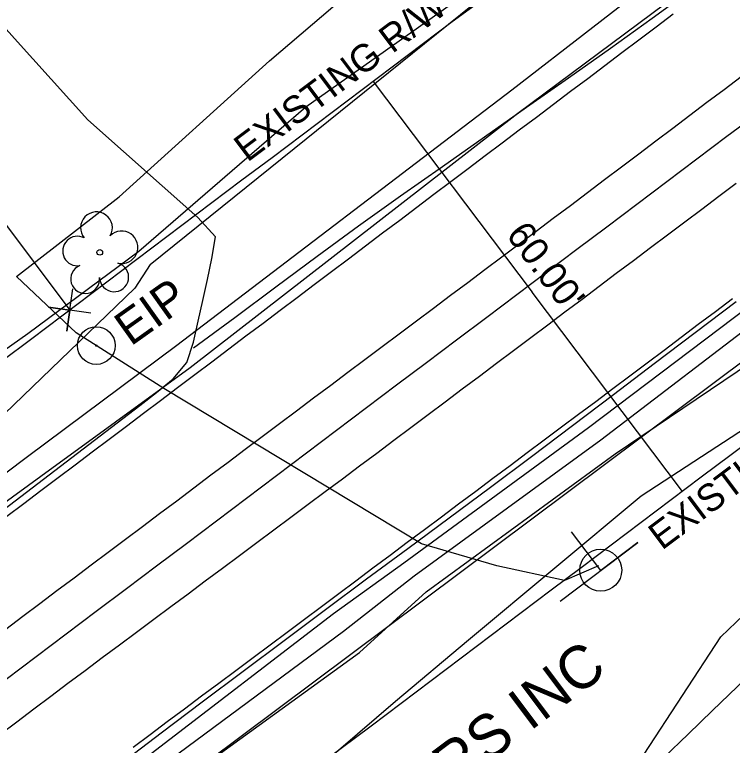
# Model space of a CAD drawing. Extents: x 2186615 to 2188822, y 629899 to 631820.
# Drawn here: x 2186940.8 to 2187024.7, y 630222.6 to 630308 of the extents above; entities that cross this region are included whole.
import ezdxf

# ---------------------------------------------------------------- set-up
doc = ezdxf.new("R2010")
doc.units = 0
for name, color, linetype in [('Exist Horizontal Alignment', 7, 'Continuous'), ('Exist Property Corner CELL', 7, 'Continuous'), ('Exist Property Iron Pin CELL', 7, 'Continuous'), ('Exist Property Iron Pin Text', 7, 'Continuous'), ('Exist Property Line', 7, 'Continuous'), ('Exist Property Owner Text', 7, 'Continuous'), ('Exist Right of Way Line', 7, 'Continuous'), ('Exist Right of Way Line Text', 7, 'Continuous'), ('Exist Right of Way Width CELL', 7, 'Continuous'), ('Exist Roads EOP', 7, 'Continuous'), ('Exist Roads EOP Other', 7, 'Continuous'), ('Exist Roads EOT', 7, 'Continuous'), ('Exist Utilities Gas UG Line SUE LOS B', 7, 'Continuous'), ('Exist Utilities Power Joint Use Telephone CELL', 7, 'Continuous'), ('Exist Utilities Sanitary Sewer UG Line', 7, 'Continuous'), ('Exist Utilities Telephone UG Cable SUE LOS C', 7, 'Continuous'), ('Exist Utilities Telephone UG FO SUE LOS B', 7, 'Continuous'), ('Exist Utilities TV UG Cable SUE LOS B', 7, 'Continuous'), ('Exist Utilities TV UG FO Cable SUE LOS B', 7, 'Continuous'), ('Exist Utilities Water UG Line SUE LOS B', 7, 'Continuous'), ('Exist Vegetation Tree CELL', 7, 'Continuous'), ('Exist Vegetation Woods Line', 7, 'Continuous'), ('Scratch_Level_1', 7, 'Continuous')]:
    doc.layers.add(name, color=color, linetype=linetype)

msp = doc.modelspace()

# ---------------------------------------------------------------- linework, layer by layer
at = {"layer": 'Exist Horizontal Alignment'}
msp.add_arc((2232330.704, 570095.737), 75342.476, 126.85926308, 127.07301977, dxfattribs=at)
at = {"layer": 'Exist Property Corner CELL'}
msp.add_line((2186947.272, 630273.425), (2186947.272, 630273.425), dxfattribs=at)
msp.add_lwpolyline([(2186949.746, 630273.07), (2186944.797, 630273.781), (2186947.272, 630273.425), (2186946.916, 630270.951), (2186947.627, 630275.9)], dxfattribs=at)
at = {"layer": 'Exist Property Iron Pin CELL'}
for radius in [2.203, 0.0707]:
    msp.add_circle((2186950.378, 630269.278), radius, dxfattribs=at)
at = {"layer": 'Exist Property Line'}
msp.add_line((2186817.153, 630447.151), (2186947.272, 630273.425), dxfattribs=at)
at = {"layer": 'Exist Right of Way Line'}
for centre, radius, start, end in [((2189028.8, 628141.736), 2893.554, 125.65722, 135.708207), ((2232330.704, 570095.737), 75372.476, 126.85926308, 127.07301977), ((2232330.704, 570095.737), 75312.476, 126.85926308, 127.07301977)]:
    msp.add_arc(centre, radius, start, end, dxfattribs=at)
at = {"layer": 'Exist Right of Way Width CELL'}
for p in [(2186982.724, 630300.145), (2187018.823, 630252.22)]:
    msp.add_line(p, (2187001.279, 630275.511), dxfattribs=at)
at = {"layer": 'Exist Roads EOP'}
for points in [[(2186961.722, 630269.005), (2186966.542, 630272.577), (2186971.362, 630276.149), (2186976.183, 630279.718), (2186981.013, 630283.275), (2186985.89, 630286.768), (2186990.796, 630290.22), (2186995.703, 630293.671), (2187000.61, 630297.122), (2187005.515, 630300.577), (2187010.416, 630304.037), (2187015.298, 630307.524), (2187020.127, 630311.083)], [(2186939.56, 630250.133), (2186941.546, 630251.649), (2186943.532, 630253.165), (2186945.518, 630254.682), (2186947.503, 630256.198), (2186949.489, 630257.715), (2186951.474, 630259.233), (2186953.459, 630260.752), (2186955.441, 630262.273), (2186957.419, 630263.801), (2186959.352, 630265.385), (2186960.941, 630267.309), (2186961.723, 630269.679), (2186962.287, 630272.115), (2186962.835, 630274.554), (2186963.362, 630276.997), (2186963.853, 630279.448), (2186964.3, 630282.004)], [(2187025.121, 630274.377), (2187020.333, 630270.762), (2187015.546, 630267.147), (2187010.763, 630263.527), (2187005.981, 630259.905), (2187001.199, 630256.283), (2186996.408, 630252.675), (2186991.587, 630249.107), (2186986.764, 630245.541), (2186981.944, 630241.973), (2186977.139, 630238.384), (2186972.335, 630234.793), (2186967.532, 630231.203), (2186962.743, 630227.593), (2186957.963, 630223.972), (2186953.183, 630220.351)]]:
    msp.add_lwpolyline(points, dxfattribs=at)
at = {"layer": 'Exist Roads EOP Other'}
for p, q in [((2186962.235, 630284.243), (2186949.393, 630295.672)), ((2186964.3, 630282.004), (2186962.235, 630284.243))]:
    msp.add_line(p, q, dxfattribs=at)
msp.add_lwpolyline([(2186925.022, 630323.205), (2186930.536, 630316.971), (2186934.644, 630312.092), (2186940.815, 630305.172), (2186949.393, 630295.672)], dxfattribs=at)
at = {"layer": 'Exist Roads EOT'}
for points in [[(2186939.924, 630249.331), (2186941.919, 630250.835), (2186943.914, 630252.34), (2186945.909, 630253.845), (2186947.904, 630255.349), (2186949.899, 630256.854), (2186951.894, 630258.359), (2186953.889, 630259.863), (2186955.885, 630261.368), (2186957.88, 630262.873), (2186959.875, 630264.378), (2186961.871, 630265.883), (2186963.866, 630267.388), (2186965.861, 630268.893), (2186967.856, 630270.399), (2186969.851, 630271.904), (2186971.847, 630273.409), (2186973.842, 630274.915), (2186975.837, 630276.42), (2186977.832, 630277.925), (2186979.828, 630279.43), (2186981.823, 630280.936), (2186983.818, 630282.441), (2186985.813, 630283.946), (2186987.809, 630285.451), (2186989.804, 630286.956), (2186991.8, 630288.462), (2186993.795, 630289.967), (2186995.791, 630291.472), (2186997.786, 630292.977), (2186999.782, 630294.482), (2187001.777, 630295.987), (2187003.773, 630297.493), (2187005.768, 630298.998), (2187007.764, 630300.503), (2187009.76, 630302.008), (2187011.755, 630303.514), (2187013.751, 630305.019), (2187015.746, 630306.525), (2187017.742, 630308.03)], [(2186939.795, 630236.14), (2186941.791, 630237.643), (2186943.789, 630239.144), (2186945.786, 630240.645), (2186947.784, 630242.146), (2186949.782, 630243.647), (2186951.78, 630245.148), (2186953.777, 630246.649), (2186955.775, 630248.15), (2186957.773, 630249.651), (2186959.771, 630251.152), (2186961.769, 630252.653), (2186963.767, 630254.154), (2186965.765, 630255.655), (2186967.763, 630257.156), (2186969.761, 630258.657), (2186971.759, 630260.159), (2186973.758, 630261.659), (2186975.757, 630263.159), (2186977.757, 630264.659), (2186979.756, 630266.158), (2186981.756, 630267.658), (2186983.755, 630269.158), (2186985.755, 630270.658), (2186987.754, 630272.157), (2186989.754, 630273.657), (2186991.753, 630275.157), (2186993.753, 630276.656), (2186995.752, 630278.156), (2186997.752, 630279.656), (2186999.751, 630281.156), (2187001.75, 630282.656), (2187003.747, 630284.16), (2187005.743, 630285.665), (2187007.737, 630287.171), (2187009.732, 630288.678), (2187011.727, 630290.184), (2187013.721, 630291.69), (2187015.716, 630293.197), (2187017.71, 630294.703), (2187019.705, 630296.21), (2187021.7, 630297.716), (2187023.695, 630299.222), (2187025.689, 630300.729)], [(2186939.082, 630223.815), (2186941.078, 630225.317), (2186943.075, 630226.82), (2186945.071, 630228.322), (2186947.069, 630229.822), (2186949.07, 630231.32), (2186951.072, 630232.814), (2186953.076, 630234.307), (2186955.08, 630235.8), (2186957.083, 630237.293), (2186959.087, 630238.786), (2186961.091, 630240.279), (2186963.095, 630241.772), (2186965.098, 630243.265), (2186967.102, 630244.758), (2186969.106, 630246.251), (2186971.11, 630247.744), (2186973.114, 630249.237), (2186975.118, 630250.73), (2186977.122, 630252.224), (2186979.124, 630253.719), (2186981.125, 630255.217), (2186983.124, 630256.717), (2186985.123, 630258.217), (2186987.122, 630259.718), (2186989.121, 630261.218), (2186991.119, 630262.718), (2186993.118, 630264.219), (2186995.117, 630265.719), (2186997.116, 630267.219), (2186999.115, 630268.719), (2187001.114, 630270.22), (2187003.113, 630271.72), (2187005.112, 630273.221), (2187007.112, 630274.721), (2187009.111, 630276.221), (2187011.109, 630277.722), (2187013.107, 630279.225), (2187015.104, 630280.727), (2187017.101, 630282.231), (2187019.098, 630283.734), (2187021.096, 630285.237), (2187023.093, 630286.74), (2187025.09, 630288.243)], [(2187024.681, 630274.737), (2187022.684, 630273.233), (2187020.687, 630271.73), (2187018.69, 630270.226), (2187016.694, 630268.722), (2187014.697, 630267.218), (2187012.699, 630265.716), (2187010.699, 630264.217), (2187008.698, 630262.719), (2187006.697, 630261.222), (2187004.696, 630259.724), (2187002.695, 630258.226), (2187000.694, 630256.729), (2186998.693, 630255.231), (2186996.692, 630253.734), (2186994.692, 630252.236), (2186992.691, 630250.739), (2186990.69, 630249.242), (2186988.689, 630247.744), (2186986.689, 630246.246), (2186984.688, 630244.749), (2186982.688, 630243.251), (2186980.687, 630241.753), (2186978.687, 630240.256), (2186976.686, 630238.758), (2186974.686, 630237.261), (2186972.685, 630235.764), (2186970.684, 630234.268), (2186968.682, 630232.773), (2186966.679, 630231.279), (2186964.677, 630229.784), (2186962.675, 630228.289), (2186960.672, 630226.794), (2186958.67, 630225.3), (2186956.668, 630223.805), (2186954.665, 630222.311)]]:
    msp.add_lwpolyline(points, dxfattribs=at)
at = {"layer": 'Exist Utilities Gas UG Line SUE LOS B'}
for points in [[(2186961.336, 630266.711), (2186999.602, 630296.447), (2187019.951, 630311.635), (2187033.399, 630322.075), (2187051.697, 630335.616), (2187070.686, 630349.818), (2187099.686, 630372.441), (2187126.474, 630392.391)], [(2186901.329, 630223.037), (2186914.714, 630232.621), (2186925.868, 630240.886), (2186943.9, 630254.026), (2186961.336, 630266.711)]]:
    msp.add_lwpolyline(points, dxfattribs=at)
at = {"layer": 'Exist Utilities Power Joint Use Telephone CELL'}
msp.add_line((2187009.288, 630243.022), (2187009.288, 630243.022), dxfattribs=at)
msp.add_lwpolyline([(2187004.562, 630239.427), (2187013.609, 630246.261), (2187009.3, 630243.006), (2187005.883, 630247.499)], dxfattribs=at)
msp.add_circle((2187009.285, 630243.028), 2.45, dxfattribs=at)
at = {"layer": 'Exist Utilities Sanitary Sewer UG Line'}
msp.add_line((2186953.526, 630213.342), (2187280.261, 630457.751), dxfattribs=at)
at = {"layer": 'Exist Utilities Telephone UG Cable SUE LOS C'}
for points in [[(2186993.862, 630234.892), (2187014.015, 630251.722), (2187026.326, 630259.734), (2187038.967, 630268.514), (2187049.587, 630278.035), (2187058.856, 630284.432), (2187076.233, 630285.219)], [(2186988.908, 630240.518), (2187010.986, 630256.618), (2187031.554, 630270.541), (2187036.316, 630271.727), (2187040.709, 630270.129), (2187048.711, 630267.562)], [(2186925.083, 630191.44), (2186942.75, 630202.332), (2186952.607, 630209.213), (2186959.238, 630217.539), (2186981.103, 630233.396), (2186988.908, 630240.518)], [(2186929.027, 630186.195), (2186933.467, 630189.363), (2186946.683, 630197.487), (2186956.688, 630203.768), (2186965.353, 630210.548), (2186985.308, 630227.732), (2186993.862, 630234.892)]]:
    msp.add_lwpolyline(points, dxfattribs=at)
at = {"layer": 'Exist Utilities Telephone UG FO SUE LOS B'}
for points in [[(2186916.21, 630248.602), (2186927.377, 630260.091), (2186942.373, 630270.681), (2186955.344, 630280.323), (2186974.856, 630297.179), (2186993.469, 630310.392), (2187007.028, 630317.718), (2187027.998, 630334.099), (2187044.496, 630346.393), (2187064.767, 630361.141), (2187093.151, 630381.244), (2187121.863, 630401.099)], [(2186986.295, 630243.894), (2187007.861, 630259.716), (2187028.276, 630275.112), (2187042.806, 630286.802), (2187056.536, 630295.904), (2187062.362, 630297.624), (2187066.496, 630293.81), (2187076.233, 630285.219)], [(2186987.506, 630242.361), (2187009.305, 630258.272), (2187029.28, 630273.535), (2187036.206, 630277.824), (2187039.143, 630277.431), (2187049.385, 630270.146)], [(2186921.881, 630195.7), (2186938.731, 630207.735), (2186949.001, 630215.649), (2186956.781, 630221.623), (2186978.081, 630237.971), (2186986.295, 630243.894)], [(2186922.887, 630194.362), (2186939.612, 630206.665), (2186949.682, 630213.944), (2186957.968, 630220.123), (2186979.262, 630235.892), (2186987.506, 630242.361)]]:
    msp.add_lwpolyline(points, dxfattribs=at)
at = {"layer": 'Exist Utilities TV UG Cable SUE LOS B'}
msp.add_lwpolyline([(2187009.038, 630243.535), (2187005.057, 630241.808), (2186997.151, 630243.52), (2186988.342, 630246.092), (2186958.256, 630264.279), (2186948.021, 630270.761), (2186941.052, 630277.353), (2186953.047, 630286.674), (2186970.617, 630302.565), (2186987.786, 630317.228), (2186999.435, 630326.737), (2187020.888, 630345.03), (2187036.718, 630358.422), (2187055.34, 630373.053), (2187084.13, 630394.807), (2187116.074, 630419.881)], dxfattribs=at)
at = {"layer": 'Exist Utilities TV UG FO Cable SUE LOS B'}
for points in [[(2186956.68, 630278.764), (2186994.31, 630309.111), (2187006.186, 630319.063), (2187027.034, 630336.523), (2187042.653, 630349.621), (2187062.086, 630364.95), (2187089.065, 630387.06), (2187116.728, 630410.236)], [(2186956.68, 630278.764), (2186954.885, 630276.003), (2186939.653, 630261.284), (2186920.239, 630246.775), (2186914.299, 630245.069), (2186904.328, 630239.288), (2186893.694, 630233.193)]]:
    msp.add_lwpolyline(points, dxfattribs=at)
at = {"layer": 'Exist Utilities Water UG Line SUE LOS B'}
for points in [[(2186959.767, 630269.323), (2186998.897, 630299.182), (2187017.818, 630313.833), (2187031.57, 630324.405), (2187049.452, 630337.669), (2187068.609, 630351.557), (2187098.384, 630374.128), (2187124.774, 630395.09)], [(2186899.873, 630224.973), (2186913.369, 630235.1), (2186924.427, 630242.835), (2186942.322, 630256.302), (2186959.767, 630269.323)]]:
    msp.add_lwpolyline(points, dxfattribs=at)
at = {"layer": 'Exist Vegetation Tree CELL'}
msp.add_line((2186950.783, 630280.17), (2186950.783, 630280.17), dxfattribs=at)
msp.add_circle((2186950.783, 630280.17), 0.326, dxfattribs=at)
for centre, radius, start, end in [((2186950.399, 630283.043), 1.856, 330.16508, 219.71335), ((2186953.332, 630280.759), 1.899, 257.1011, 134.19993), ((2186948.178, 630280.324), 1.727, 62.66361, 279.3457), ((2186949.079, 630277.049), 1.689, 111.56708, 6.23104), ((2186952.456, 630277.27), 1.698, 181.28216, 74.55999)]:
    msp.add_arc(centre, radius, start, end, dxfattribs=at)
at = {"layer": 'Exist Vegetation Woods Line'}
msp.add_lwpolyline([(2186944.379, 630160.412), (2186956.197, 630164.929), (2186962.271, 630168.27), (2186984.343, 630188.213), (2187009.886, 630214.679), (2187023.297, 630235.224), (2187047.498, 630258.381), (2187065.129, 630270.937)], dxfattribs=at)
at = {"layer": 'Scratch_Level_1'}
msp.add_arc((2189028.8, 628141.736), 2815.554, 125.65722, 135.708207, dxfattribs=at)

# ---------------------------------------------------------------- texts
at = {"layer": 'Exist Property Iron Pin Text'}
msp.add_text('EIP', height=4, rotation=35.42846, dxfattribs=at).set_placement((2186954.394, 630269.135))
at = {"layer": 'Exist Property Owner Text'}
msp.add_text('CAROLINA PACKERS INC', height=5, rotation=36.85926, dxfattribs=at).set_placement((2186945.131, 630182.265))
at = {"layer": 'Exist Right of Way Line Text'}
for rotation, p in [(36.90456, (2186968.024, 630290.636)), (36.89538, (2187016.429, 630245.292))]:
    msp.add_text('EXISTING R/W', height=3.2, rotation=rotation, dxfattribs=at).set_placement(p)
at = {"layer": 'Exist Right of Way Width CELL'}
msp.add_text("60.00'", height=3.2, rotation=306.98829, dxfattribs=at).set_placement((2186998.146, 630282.205))

doc.saveas('drawing.dxf')
